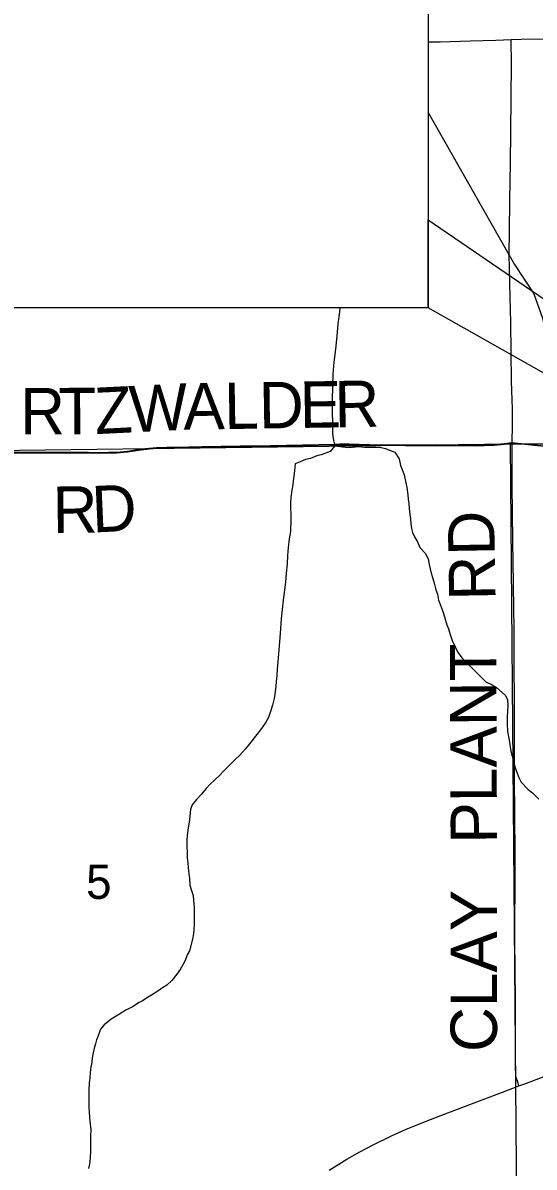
# Model space of a CAD drawing. Extents: x 0 to 34, y 0 to 22.
# Drawn here: x 4.826 to 5.452, y 17.529 to 18.929 of the extents above; entities that cross this region are included whole.
import ezdxf

# ---------------------------------------------------------------- set-up
doc = ezdxf.new("R2010")
doc.units = 0
for name, color, linetype in [('Default', 7, 'Continuous'), ('GM_X_Minor_River', 7, 'Continuous'), ('GM_X_Rail_Line', 7, 'Continuous'), ('GM_X_Section', 7, 'Continuous'), ('GM_X_Section_Text', 7, 'Continuous'), ('GM_X_State_Route', 7, 'Continuous'), ('GM_X_Township_Road', 7, 'Continuous'), ('GM_X_Township_Road_Text', 7, 'Continuous'), ('SH_Text', 7, 'Continuous')]:
    doc.layers.add(name, color=color, linetype=linetype)

msp = doc.modelspace()

# ---------------------------------------------------------------- linework, layer by layer
at = {"layer": 'Default'}
msp.add_lwpolyline([(5.3223, 18.688), (6.2262, 18.0698), (5.3223, 18.5805)], close=True, dxfattribs=at)
for points in [[(5.4679, 18.4109), (5.4247, 18.4153), (5.4152, 18.4142), (5.4028, 18.4129), (5.3905, 18.4123), (5.3811, 18.4121), (5.3467, 18.4124), (5.3314, 18.4123), (5.2942, 18.4125), (5.2506, 18.4129), (5.2257, 18.4134), (5.2142, 18.4134), (5.2074, 18.4133), (5.1884, 18.4129), (5.1293, 18.4116), (5.0923, 18.4111), (5.0456, 18.4103), (5.03, 18.4099), (5.0023, 18.4096), (4.9897, 18.4092), (4.9805, 18.4085), (4.9682, 18.407), (4.9597, 18.4055), (4.9543, 18.4047), (4.9408, 18.4036), (4.9312, 18.4033), (4.9179, 18.4032), (4.9065, 18.4034), (4.8845, 18.4033), (4.8287, 18.4036), (4.7759, 18.4035)], [(4.7759, 18.4035), (4.8287, 18.4036), (4.8845, 18.4033), (4.9065, 18.4034), (4.9179, 18.4032), (4.9312, 18.4033), (4.9408, 18.4036), (4.9543, 18.4047), (4.9597, 18.4055), (4.9682, 18.407), (4.9805, 18.4085), (4.9897, 18.4092), (5.0023, 18.4096), (5.03, 18.4099), (5.0456, 18.4103), (5.0923, 18.4111), (5.1293, 18.4116), (5.1884, 18.4129), (5.2074, 18.4133), (5.2142, 18.4134), (5.2257, 18.4134), (5.2506, 18.4129), (5.2942, 18.4125), (5.3314, 18.4123), (5.3467, 18.4124), (5.3811, 18.4121), (5.3905, 18.4123), (5.4028, 18.4129), (5.4152, 18.4142), (5.4247, 18.4153), (5.4679, 18.4109)]]:
    msp.add_lwpolyline(points, dxfattribs=at)
at = {"layer": 'GM_X_Minor_River'}
for points in [[(5.2142, 18.5805), (5.2137, 18.5753), (5.2118, 18.5608), (5.2103, 18.5456), (5.2088, 18.53), (5.2069, 18.514), (5.2055, 18.4992), (5.2051, 18.484), (5.2048, 18.4684), (5.2048, 18.4532), (5.2052, 18.4387), (5.2052, 18.4266), (5.2064, 18.4182), (5.208, 18.4114), (5.2022, 18.4045), (5.1912, 18.4004), (5.1858, 18.3992), (5.1782, 18.3962), (5.1721, 18.3947), (5.1656, 18.392), (5.1595, 18.3897), (5.1588, 18.3814), (5.158, 18.3741), (5.1569, 18.3688), (5.1565, 18.3639), (5.1554, 18.3574), (5.1543, 18.3483), (5.1539, 18.3414), (5.154, 18.322), (5.1536, 18.3068), (5.1521, 18.2977), (5.151, 18.2871), (5.1503, 18.2772), (5.1495, 18.2673), (5.1484, 18.2559), (5.1477, 18.2448), (5.1447, 18.2228), (5.1424, 18.2), (5.1417, 18.1878), (5.1406, 18.1772), (5.1398, 18.1669), (5.1391, 18.157), (5.1384, 18.1475), (5.1376, 18.1384), (5.1369, 18.1304), (5.1361, 18.1232), (5.1358, 18.1171), (5.1346, 18.1076), (5.1339, 18.1026), (5.1316, 18.0943), (5.1294, 18.0867), (5.1267, 18.0794), (5.1237, 18.0734), (5.1183, 18.0658), (5.1054, 18.049), (5.0985, 18.0403), (5.0917, 18.0331), (5.086, 18.0277), (5.0723, 18.0141), (5.067, 18.0084), (5.0612, 18.003), (5.0551, 17.9973), (5.0506, 17.9924), (5.0449, 17.9856), (5.0388, 17.9787), (5.0335, 17.9723), (5.0316, 17.9666), (5.0308, 17.959), (5.0301, 17.9536), (5.0286, 17.9441), (5.0274, 17.935), (5.0271, 17.9293), (5.0271, 17.9213), (5.0275, 17.9141), (5.0275, 17.9076), (5.0283, 17.9012), (5.0287, 17.8958), (5.0295, 17.8875), (5.0302, 17.8825), (5.0306, 17.8742), (5.0322, 17.8688), (5.0345, 17.8616), (5.0353, 17.8555), (5.036, 17.8468), (5.0361, 17.8255), (5.0357, 17.8198), (5.035, 17.8145), (5.0338, 17.808), (5.0304, 17.7939), (5.0274, 17.789), (5.0251, 17.7818), (5.0221, 17.7768), (5.0187, 17.7711), (5.0149, 17.7654), (5.0084, 17.7574)], [(5.208, 18.4114), (5.224, 18.4095), (5.2297, 18.4098), (5.237, 18.4106), (5.2442, 18.4098), (5.2583, 18.4098), (5.2648, 18.4094), (5.2698, 18.4083), (5.2748, 18.4064), (5.2816, 18.4037), (5.2866, 18.3957), (5.2885, 18.3877), (5.2905, 18.3828), (5.2928, 18.376), (5.2947, 18.3661), (5.2959, 18.3604), (5.2974, 18.3516), (5.2978, 18.3463), (5.2986, 18.341), (5.299, 18.3349), (5.2997, 18.3277), (5.3005, 18.3223), (5.3009, 18.3162), (5.3017, 18.3105), (5.3032, 18.3056), (5.3055, 18.3003), (5.309, 18.2942), (5.3121, 18.287), (5.3186, 18.2801), (5.322, 18.2733), (5.3236, 18.2664), (5.3259, 18.2558), (5.3278, 18.2493), (5.3297, 18.2436), (5.3316, 18.2352), (5.3336, 18.2299), (5.3347, 18.2227), (5.3386, 18.2132), (5.3405, 18.2078), (5.342, 18.2025), (5.3451, 18.1926), (5.347, 18.1877), (5.349, 18.1808), (5.3516, 18.1736), (5.3555, 18.1649), (5.3582, 18.1595), (5.3635, 18.1523), (5.3693, 18.1462), (5.3758, 18.1401), (5.3872, 18.1287), (5.3926, 18.123), (5.4006, 18.1192), (5.4056, 18.1158), (5.4163, 18.1067), (5.4194, 18.1013), (5.4198, 18.0933), (5.4194, 18.0873), (5.4187, 18.0796), (5.4187, 18.0717), (5.4191, 18.0622), (5.4214, 18.0515), (5.4233, 18.0382), (5.4249, 18.0321), (5.4264, 18.0253), (5.4287, 18.0177), (5.4306, 18.0123), (5.4326, 18.0066), (5.436, 18.0002), (5.4441, 17.9914), (5.4502, 17.9865), (5.4574, 17.9792)], [(5.0084, 17.7574), (5.0023, 17.7517), (4.997, 17.7483), (4.9916, 17.7445), (4.9836, 17.7396), (4.9787, 17.7365), (4.9737, 17.7331), (4.9688, 17.7304), (4.9604, 17.7251), (4.9524, 17.721), (4.9444, 17.7164), (4.9345, 17.7103), (4.9257, 17.7031), (4.9215, 17.6978), (4.9185, 17.6898), (4.9166, 17.6848), (4.9151, 17.6799), (4.9136, 17.6746), (4.9124, 17.6689), (4.9113, 17.6628), (4.9106, 17.6575), (4.9094, 17.6514), (4.9087, 17.6449), (4.9083, 17.6385), (4.9076, 17.632), (4.9072, 17.6232), (4.9072, 17.6137), (4.9069, 17.608), (4.9069, 17.602), (4.9073, 17.5963), (4.9077, 17.5902), (4.9084, 17.5848), (4.9096, 17.5757), (4.9092, 17.5666), (4.9093, 17.5575), (4.9089, 17.5491), (4.9085, 17.54), (4.9078, 17.5327), (4.9067, 17.5274)]]:
    msp.add_lwpolyline(points, dxfattribs=at)
at = {"layer": 'GM_X_Rail_Line'}
msp.add_lwpolyline([(5.3223, 18.8195), (5.4276, 18.6336), (5.4516, 18.5976), (5.462, 18.5676), (5.468, 18.5406), (5.4695, 18.5137), (5.4725, 18.1255), (5.4814, 18.07), (5.4919, 18.0086), (5.5024, 17.9621), (5.5234, 17.9081), (5.6581, 17.6099), (5.724, 17.457), (5.7449, 17.406), (5.7674, 17.3506), (5.7973, 17.2561), (5.8333, 17.1242), (5.8662, 16.9938), (5.8901, 16.8859), (5.8901, 16.8575), (5.8886, 16.8335), (5.7201, 16.39)], dxfattribs=at)
at = {"layer": 'GM_X_Section'}
for points in [[(4.4724, 18.5805), (4.4738, 18.4018), (5.4223, 18.414), (5.4724, 18.4134), (5.472, 19.4291), (4.4662, 19.4189), (4.4671, 19.2976), (5.3223, 19.2976), (5.3223, 18.5805)], [(4.4738, 18.4018), (5.4223, 18.414), (5.4312, 17.3835), (4.419, 17.3654), (4.4097, 18.4011)], [(6.4931, 17.5349), (6.4793, 18.4161), (5.4724, 18.4134), (5.4223, 18.414), (5.4312, 17.3835), (6.4908, 17.4246), (6.4908, 17.5349)]]:
    msp.add_lwpolyline(points, close=True, dxfattribs=at)
at = {"layer": 'GM_X_State_Route'}
msp.add_lwpolyline([(5.2011, 17.5256), (5.2227, 17.5389), (5.2386, 17.5478), (5.2551, 17.5564), (5.2775, 17.5674), (5.2945, 17.5751), (5.3175, 17.5845), (5.3377, 17.5924), (5.3668, 17.6034), (5.4133, 17.6208), (5.4332, 17.6284), (5.4394, 17.6307), (5.4889, 17.6494), (5.5702, 17.6802), (5.5874, 17.6872), (5.6073, 17.696), (5.6255, 17.7046)], dxfattribs=at)
at = {"layer": 'GM_X_Township_Road'}
for points in [[(5.3223, 18.9057), (5.3367, 18.906), (5.374, 18.9072), (5.405, 18.908), (5.4237, 18.9086)], [(5.4249, 18.4148), (5.4253, 18.438), (5.4253, 18.4566), (5.4242, 18.4907), (5.4233, 18.5623), (5.4226, 18.5933), (5.4216, 18.6275), (5.4213, 18.6461), (5.4218, 18.6741), (5.4222, 18.7114), (5.4228, 18.758), (5.4234, 18.7953), (5.4241, 18.8791), (5.4238, 18.9069), (5.4237, 18.9086)], [(5.4237, 18.9086), (5.4361, 18.909), (5.5013, 18.9098)], [(4.7761, 18.403), (4.8289, 18.4031), (4.8847, 18.4028), (4.9067, 18.4029), (4.9181, 18.4027), (4.9314, 18.4028), (4.941, 18.4031), (4.9545, 18.4041), (4.9599, 18.4049), (4.9684, 18.4064), (4.9807, 18.408), (4.9899, 18.4087), (5.0025, 18.4091), (5.0302, 18.4094), (5.0459, 18.4098), (5.0925, 18.4105), (5.1295, 18.411), (5.1886, 18.4123), (5.2076, 18.4128), (5.2115, 18.4128)], [(5.2115, 18.4128), (5.2145, 18.4128), (5.2259, 18.4129), (5.2508, 18.4124), (5.2944, 18.412), (5.3316, 18.4117), (5.3469, 18.4119), (5.3813, 18.4116), (5.3907, 18.4118), (5.403, 18.4124), (5.4154, 18.4137), (5.4249, 18.4148)], [(5.4332, 17.6284), (5.4321, 17.632), (5.43, 17.6388), (5.4295, 17.6412), (5.4293, 17.6446), (5.4292, 17.6484), (5.4289, 17.6676), (5.429, 17.6925), (5.4292, 17.708), (5.429, 17.7298), (5.4285, 17.7732), (5.4283, 17.8043), (5.4284, 17.8354), (5.4286, 17.8664), (5.4285, 17.8882), (5.4286, 17.9193), (5.4283, 17.9534), (5.428, 18.0125), (5.4278, 18.0435), (5.4279, 18.0684), (5.4277, 18.1026), (5.4275, 18.1398), (5.4275, 18.1523), (5.4272, 18.1895), (5.4268, 18.2113), (5.4264, 18.2428), (5.4258, 18.2955), (5.425, 18.3635), (5.425, 18.3759), (5.4251, 18.3914), (5.4249, 18.4148)]]:
    msp.add_lwpolyline(points, dxfattribs=at)
at = {"layer": 'SH_Text'}
msp.add_lwpolyline([(3.1024, 19.2976), (5.3223, 19.2976), (5.3223, 18.5805), (3.1024, 18.5805)], close=True, dxfattribs=at)

# ---------------------------------------------------------------- texts
at = {"layer": 'GM_X_Section_Text'}
msp.add_text('5', height=0.0419, rotation=0, dxfattribs=at).set_placement((4.9037, 17.8573))
at = {"layer": 'GM_X_Township_Road_Text'}
for s, height, rotation, p in [('R', 0.0568, 359.9941, (4.823, 18.4257)), ('T', 0.0568, 0.0839, (4.8698, 18.4257)), ('Z', 0.0568, 2.8036, (4.9152, 18.4258)), ('W', 0.0568, 2.8975, (4.9578, 18.4279)), ('A', 0.0568, 0.9016, (5.023, 18.4312)), ('L', 0.0568, 0.8872, (5.073, 18.432)), ('D', 0.0568, 0.8881, (5.1155, 18.4327)), ('E', 0.0568, 0.8872, (5.1655, 18.4334)), ('R', 0.0568, 0.8865, (5.208, 18.4341)), ('R', 0.0568, 0.6811, (4.8631, 18.3049)), ('D', 0.0568, 2.5438, (4.9118, 18.3055)), ('RD', 0.05682, 90.986, (5.4047, 18.2228)), ('PLANT', 0.05682, 90.2041, (5.4064, 17.925)), ('CLAY', 0.05682, 90, (5.4064, 17.67))]:
    msp.add_text(s, height=height, rotation=rotation, dxfattribs=at).set_placement(p)

doc.saveas('drawing.dxf')
